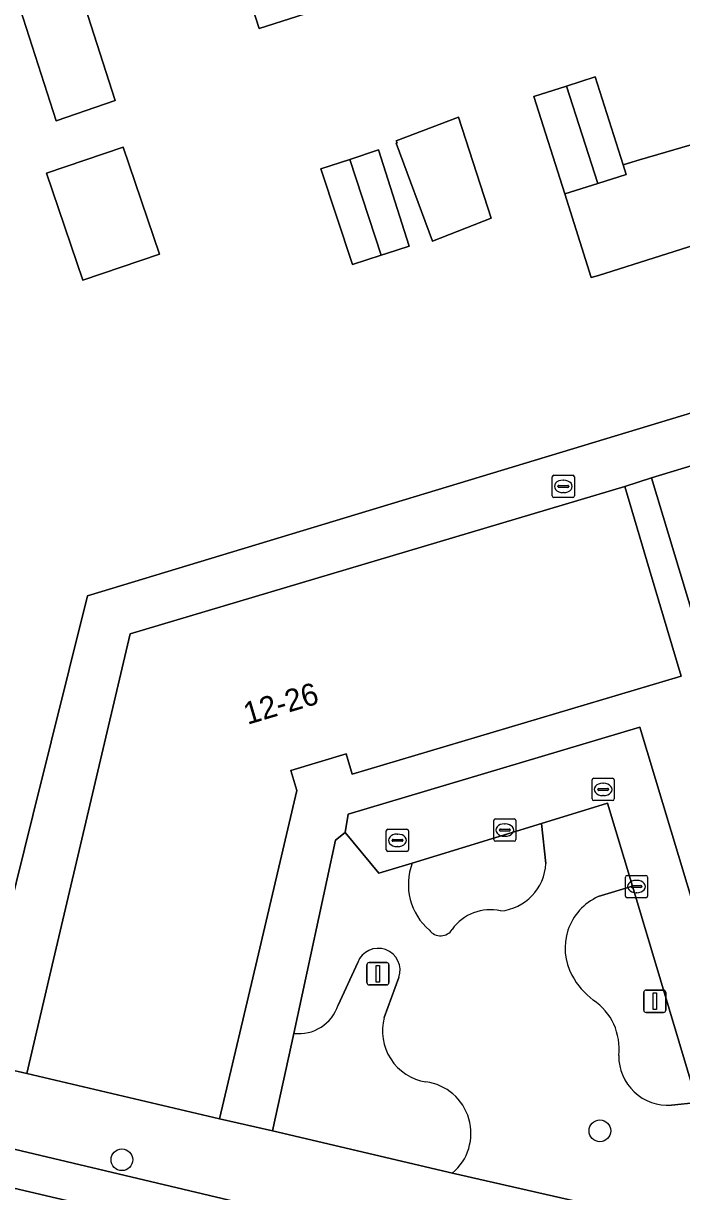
# Model space of a CAD drawing. Extents: x 159716 to 160783, y 383290 to 384031.
# Drawn here: x 160082.3 to 160111.9, y 383489.6 to 383542.1 of the extents above; entities that cross this region are included whole.
import ezdxf

# ---------------------------------------------------------------- set-up
doc = ezdxf.new("R2010")
doc.units = 0
for name, color, linetype in [('IMGEO_Boom', 7, 'Continuous'), ('IMGEO_Brandkraan', 7, 'Continuous'), ('IMGEO_Erf', 7, 'Continuous'), ('IMGEO_Groenvoorziening', 7, 'Continuous'), ('IMGEO_Hek', 7, 'Continuous'), ('IMGEO_Kolk', 7, 'Continuous'), ('IMGEO_Lichtmast', 7, 'Continuous'), ('IMGEO_Pand', 7, 'Continuous'), ('IMGEO_Pand_nummerreeks', 7, 'Continuous'), ('IMGEO_Parkeervlak_open', 7, 'Continuous'), ('IMGEO_Rijbaan_lokaal_open', 7, 'Continuous'), ('IMGEO_Rioolput', 7, 'Continuous'), ('IMGEO_Voetpad_open', 7, 'Continuous')]:
    doc.layers.add(name, color=color, linetype=linetype)

msp = doc.modelspace()

# ---------------------------------------------------------------- linework, layer by layer
at = {"layer": 'IMGEO_Boom'}
for centre in [(160108.178, 383492.298), (160086.689, 383490.997)]:
    msp.add_circle(centre, 0.489, dxfattribs=at)
at = {"layer": 'IMGEO_Brandkraan'}
for p, q in [((160106.033, 383520.85), (160106.033, 383521.702)), ((160106.108, 383521.776), (160106.96, 383521.776)), ((160106.521, 383521.556), (160106.546, 383521.556)), ((160107.034, 383521.702), (160107.034, 383520.85)), ((160106.292, 383521.27), (160106.292, 383521.282)), ((160106.73, 383521.233), (160106.332, 383521.233)), ((160106.335, 383521.319), (160106.733, 383521.319)), ((160106.544, 383520.996), (160106.519, 383520.996)), ((160106.776, 383521.282), (160106.776, 383521.27)), ((160106.96, 383520.776), (160106.108, 383520.776))]:
    msp.add_line(p, q, dxfattribs=at)
for points in [[(160106.033, 383520.85), (160106.033, 383521.702)], [(160106.108, 383521.776), (160106.96, 383521.776)], [(160107.034, 383521.702), (160107.034, 383520.85)], [(160106.96, 383520.776), (160106.108, 383520.776)]]:
    msp.add_lwpolyline(points, dxfattribs=at)
for centre, radius, start, end in [((160106.11, 383521.7), 0.0765, 91.552, 178.448), ((160106.11, 383521.7), 0.0765, 91.552, 178.448), ((160106.958, 383521.7), 0.0765, 1.552, 88.448), ((160106.958, 383521.7), 0.0765, 1.552, 88.448), ((160106.332, 383521.279), 0.0403, 85.8775, 175.7526), ((160106.329, 383521.269), 0.0366, 178.938, 274.7102), ((160106.733, 383521.276), 0.043, 264.8664, 352.4533), ((160106.737, 383521.281), 0.0386, 1.7309, 96.639), ((160106.11, 383520.852), 0.0765, 181.552, 268.448), ((160106.11, 383520.852), 0.0765, 181.552, 268.448), ((160106.958, 383520.852), 0.0765, 271.552, 358.448), ((160106.958, 383520.852), 0.0765, 271.552, 358.448)]:
    msp.add_arc(centre, radius, start, end, dxfattribs=at)
for centre, major_axis, ratio, start_param, end_param in [((160106.52, 383521.276), (-0.387, 0.002), 0.722429, 4.712389, 7.853982), ((160106.545, 383521.276), (-0.39, 0.002), 0.717154, 1.570796, 4.712389)]:
    msp.add_ellipse(centre, major_axis=major_axis, ratio=ratio, start_param=start_param, end_param=end_param, dxfattribs=at)
at = {"layer": 'IMGEO_Erf'}
for points in [[(160095.251, 383542.63), (160092.854, 383541.861), (160091.557, 383545.907)], [(160084.758, 383543.726), (160086.393, 383538.629), (160083.735, 383537.719), (160081.981, 383543.18)], [(160119.596, 383534.404), (160108.117, 383530.754), (160107.788, 383530.676), (160106.597, 383534.426), (160105.205, 383538.81), (160106.669, 383539.275), (160107.97, 383539.688), (160109.223, 383535.742), (160109.956, 383535.958), (160112.681, 383536.758)], [(160054.783, 383510.049), (160057.756, 383509.353), (160058.284, 383511.606), (160060.77, 383511.024), (160063.327, 383510.425), (160065.622, 383509.887), (160064.676, 383505.849), (160067.254, 383505.244), (160069.762, 383504.656), (160072.014, 383505.337), (160076.795, 383504.216), (160075.929, 383500.52), (160075.807, 383500), (160075.028, 383496.679), (160079.077, 383495.669), (160080.332, 383500.702), (160081.184, 383500.489), (160082.679, 383506.481), (160085.14, 383516.351), (160119.521, 383526.767)], [(160117.025, 383500), (160110.499, 383521.668), (160109.297, 383521.265), (160110.41, 383517.529), (160111.837, 383512.736), (160097.044, 383508.33), (160096.772, 383509.244), (160094.291, 383508.505), (160094.559, 383507.608), (160092.767, 383500), (160091.079, 383492.832), (160093.463, 383492.298), (160094.412, 383496.681), (160096.292, 383505.366), (160096.728, 383505.71), (160096.86, 383506.543), (160109.974, 383510.449), (160113.121, 383500)]]:
    msp.add_lwpolyline(points, dxfattribs=at)
for points in [[(160100.649, 383532.303), (160099.023, 383536.712), (160099.059, 383536.725), (160099.023, 383536.822), (160101.819, 383537.877), (160103.292, 383533.33)], [(160084.938, 383530.553), (160083.307, 383535.366), (160086.745, 383536.531), (160088.376, 383531.719)], [(160098.577, 383531.749), (160098.349, 383531.674), (160097.053, 383531.247), (160095.634, 383535.552), (160096.93, 383535.979), (160098.225, 383536.406), (160099.609, 383532.076)]]:
    msp.add_lwpolyline(points, close=True, dxfattribs=at)
at = {"layer": 'IMGEO_Groenvoorziening'}
for points in [[(160108.104, 383502.829), (160109.64, 383503.302), (160108.524, 383507.029), (160105.557, 383506.121), (160105.748, 383504.322)], [(160105.748, 383504.322), (160105.557, 383506.121), (160099.742, 383504.34)], [(160099.742, 383504.34), (160098.239, 383503.88), (160096.728, 383505.71), (160096.292, 383505.366), (160094.412, 383496.681)], [(160111.391, 383493.449), (160112.552, 383493.574), (160109.64, 383503.302), (160108.104, 383502.829)], [(160096.407, 383497.955), (160097.289, 383499.862)], [(160097.289, 383499.862), (160096.407, 383497.955)], [(160099.137, 383499.191), (160098.483, 383497.399)], [(160098.483, 383497.399), (160099.137, 383499.191)], [(160094.412, 383496.681), (160093.463, 383492.298), (160101.544, 383490.395)], [(160101.544, 383490.395), (160113.66, 383487.636), (160114.386, 383487.449), (160112.552, 383493.574), (160111.391, 383493.449)]]:
    msp.add_lwpolyline(points, dxfattribs=at)
for centre, radius, start, end in [((160102.281, 383503.38), 2.715, 159.2868, 229.5507), ((160102.281, 383503.38), 2.715, 159.2868, 229.5507), ((160103.498, 383504.426), 2.253, 275.4615, 357.365), ((160103.498, 383504.426), 2.253, 275.4615, 357.365), ((160109.158, 383500.51), 2.547, 114.4441, 208.618), ((160109.158, 383500.51), 2.547, 114.4441, 208.618), ((160103.234, 383500.172), 2.067, 76.6355, 145.1567), ((160103.234, 383500.172), 2.067, 76.6355, 145.1567), ((160101.015, 383501.693), 0.624, 217.455, 326.9329), ((160101.015, 383501.693), 0.624, 217.455, 326.9329), ((160098.211, 383499.522), 0.983, 340.3213, 159.7672), ((160098.211, 383499.522), 0.983, 340.3213, 159.7672), ((160109.951, 383500.93), 3.444, 208.4274, 233.0794), ((160109.951, 383500.93), 3.444, 208.4274, 233.0794), ((160094.645, 383498.516), 1.849, 262.7728, 342.3515), ((160094.645, 383498.516), 1.849, 262.7728, 342.3515), ((160106.403, 383495.989), 2.64, 353.2992, 55.9273), ((160106.403, 383495.989), 2.64, 353.2992, 55.9273), ((160100.718, 383496.789), 2.316, 164.7422, 261.0912), ((160100.718, 383496.789), 2.316, 164.7422, 261.0912), ((160111.241, 383495.66), 2.216, 179.4449, 273.8937), ((160111.241, 383495.66), 2.216, 179.4449, 273.8937), ((160100.048, 383492.187), 2.334, 309.8482, 82.3483), ((160100.048, 383492.187), 2.334, 309.8482, 82.3483)]:
    msp.add_arc(centre, radius, start, end, dxfattribs=at)
at = {"layer": 'IMGEO_Hek'}
msp.add_lwpolyline([(160109.956, 383535.958), (160109.223, 383535.742)], dxfattribs=at)
at = {"layer": 'IMGEO_Kolk'}
for p, q in [((160103.477, 383506.323), (160104.329, 383506.323)), ((160103.402, 383505.397), (160103.402, 383506.249)), ((160103.661, 383505.817), (160103.661, 383505.829)), ((160104.099, 383505.78), (160103.701, 383505.78)), ((160103.704, 383505.866), (160104.102, 383505.866)), ((160103.89, 383506.103), (160103.915, 383506.103)), ((160104.145, 383505.829), (160104.145, 383505.817)), ((160104.403, 383506.249), (160104.403, 383505.397)), ((160104.329, 383505.323), (160103.477, 383505.323)), ((160103.913, 383505.543), (160103.888, 383505.543)), ((160109.323, 383502.856), (160109.323, 383503.708)), ((160109.398, 383503.782), (160110.25, 383503.782)), ((160110.324, 383503.708), (160110.324, 383502.856)), ((160109.582, 383503.276), (160109.582, 383503.288)), ((160110.02, 383503.239), (160109.622, 383503.239)), ((160109.625, 383503.325), (160110.023, 383503.325)), ((160109.811, 383503.562), (160109.836, 383503.562)), ((160110.066, 383503.288), (160110.066, 383503.276)), ((160110.25, 383502.782), (160109.398, 383502.782)), ((160109.834, 383503.002), (160109.809, 383503.002))]:
    msp.add_line(p, q, dxfattribs=at)
for points in [[(160103.477, 383506.323), (160104.329, 383506.323)], [(160103.402, 383505.397), (160103.402, 383506.249)], [(160104.403, 383506.249), (160104.403, 383505.397)], [(160104.329, 383505.323), (160103.477, 383505.323)], [(160109.323, 383502.856), (160109.323, 383503.708)], [(160109.398, 383503.782), (160110.25, 383503.782)], [(160110.324, 383503.708), (160110.324, 383502.856)], [(160110.25, 383502.782), (160109.398, 383502.782)]]:
    msp.add_lwpolyline(points, dxfattribs=at)
for centre, radius, start, end in [((160103.479, 383506.247), 0.0765, 91.552, 178.448), ((160103.479, 383506.247), 0.0765, 91.552, 178.448), ((160104.327, 383506.247), 0.0765, 1.552, 88.448), ((160104.327, 383506.247), 0.0765, 1.552, 88.448), ((160103.701, 383505.826), 0.0403, 85.8775, 175.7526), ((160103.698, 383505.816), 0.0366, 178.938, 274.7102), ((160104.102, 383505.823), 0.043, 264.8664, 352.4533), ((160104.106, 383505.828), 0.0386, 1.7309, 96.639), ((160103.479, 383505.399), 0.0765, 181.552, 268.448), ((160103.479, 383505.399), 0.0765, 181.552, 268.448), ((160104.327, 383505.399), 0.0765, 271.552, 358.448), ((160104.327, 383505.399), 0.0765, 271.552, 358.448), ((160109.4, 383503.706), 0.0765, 91.552, 178.448), ((160109.4, 383503.706), 0.0765, 91.552, 178.448), ((160110.248, 383503.706), 0.0765, 1.552, 88.448), ((160110.248, 383503.706), 0.0765, 1.552, 88.448), ((160109.622, 383503.285), 0.0403, 85.8775, 175.7526), ((160109.619, 383503.275), 0.0366, 178.938, 274.7102), ((160110.023, 383503.282), 0.043, 264.8664, 352.4533), ((160110.027, 383503.287), 0.0386, 1.7309, 96.639), ((160109.4, 383502.858), 0.0765, 181.552, 268.448), ((160109.4, 383502.858), 0.0765, 181.552, 268.448), ((160110.248, 383502.858), 0.0765, 271.552, 358.448), ((160110.248, 383502.858), 0.0765, 271.552, 358.448)]:
    msp.add_arc(centre, radius, start, end, dxfattribs=at)
for centre, major_axis, ratio, start_param, end_param in [((160103.889, 383505.823), (-0.387, 0.002), 0.722429, 4.712389, 7.853982), ((160103.914, 383505.823), (-0.39, 0.002), 0.717154, 1.570796, 4.712389), ((160109.81, 383503.282), (-0.387, 0.002), 0.722429, 4.712389, 7.853982), ((160109.835, 383503.282), (-0.39, 0.002), 0.717154, 1.570796, 4.712389)]:
    msp.add_ellipse(centre, major_axis=major_axis, ratio=ratio, start_param=start_param, end_param=end_param, dxfattribs=at)
at = {"layer": 'IMGEO_Lichtmast'}
for p, q in [((160097.705, 383498.961), (160097.705, 383499.761)), ((160097.705, 383499.761), (160097.705, 383498.961)), ((160097.805, 383499.861), (160098.595, 383499.861)), ((160098.595, 383499.861), (160097.805, 383499.861)), ((160098.695, 383499.761), (160098.695, 383498.961)), ((160098.695, 383498.961), (160098.695, 383499.761)), ((160098.595, 383498.861), (160097.805, 383498.861)), ((160097.805, 383498.861), (160098.595, 383498.861)), ((160110.151, 383497.725), (160110.151, 383498.525)), ((160110.151, 383498.525), (160110.151, 383497.725)), ((160110.251, 383498.625), (160111.041, 383498.625)), ((160111.041, 383498.625), (160110.251, 383498.625)), ((160111.141, 383498.525), (160111.141, 383497.725)), ((160111.141, 383497.725), (160111.141, 383498.525)), ((160111.041, 383497.625), (160110.251, 383497.625)), ((160110.251, 383497.625), (160111.041, 383497.625))]:
    msp.add_line(p, q, dxfattribs=at)
for points in [[(160098.125, 383499.736), (160098.275, 383499.736), (160098.275, 383498.986), (160098.125, 383498.986), (160098.125, 383499.736)], [(160110.571, 383498.5), (160110.721, 383498.5), (160110.721, 383497.75), (160110.571, 383497.75), (160110.571, 383498.5)]]:
    msp.add_lwpolyline(points, dxfattribs=at)
for centre, start, end in [((160097.805, 383499.761), 90, 180), ((160097.805, 383499.761), 90, 180), ((160098.595, 383499.761), 0, 90), ((160098.595, 383499.761), 360, 90), ((160097.805, 383498.961), 180, 270), ((160097.805, 383498.961), 180, 270), ((160098.595, 383498.961), 270, 0), ((160098.595, 383498.961), 270, 0), ((160110.251, 383498.525), 90, 180), ((160110.251, 383498.525), 90, 180), ((160111.041, 383498.525), 0, 90), ((160111.041, 383498.525), 360, 90), ((160110.251, 383497.725), 180, 270), ((160110.251, 383497.725), 180, 270), ((160111.041, 383497.725), 270, 0), ((160111.041, 383497.725), 270, 0)]:
    msp.add_arc(centre, 0.1, start, end, dxfattribs=at)
at = {"layer": 'IMGEO_Pand'}
for points in [[(160091.569, 383554.115), (160086.838, 383552.595), (160089.17, 383545.319), (160089.222, 383545.158), (160091.557, 383545.907), (160092.854, 383541.861), (160095.251, 383542.63), (160095.217, 383542.738)], [(160086.838, 383552.595), (160086.347, 383552.437), (160086.102, 383553.199), (160081.748, 383551.798), (160082.75, 383548.674), (160080.454, 383547.938), (160081.981, 383543.18), (160083.735, 383537.719), (160086.393, 383538.629), (160084.758, 383543.726), (160089.222, 383545.158), (160089.17, 383545.319)], [(160108.088, 383534.899), (160109.362, 383535.304), (160109.223, 383535.742), (160107.97, 383539.688), (160106.669, 383539.275)], [(160108.088, 383534.899), (160106.669, 383539.275), (160105.205, 383538.81), (160106.597, 383534.426)], [(160101.819, 383537.877), (160099.023, 383536.822), (160099.059, 383536.725), (160099.023, 383536.712), (160100.649, 383532.303), (160103.292, 383533.33)], [(160084.938, 383530.553), (160088.376, 383531.719), (160086.745, 383536.531), (160083.307, 383535.366)], [(160096.93, 383535.979), (160098.349, 383531.674), (160098.577, 383531.749), (160099.609, 383532.076), (160098.225, 383536.406)], [(160096.93, 383535.979), (160095.634, 383535.552), (160097.053, 383531.247), (160098.349, 383531.674)], [(160119.047, 383524.242), (160115.287, 383523.11), (160110.499, 383521.668), (160117.025, 383500), (160118.898, 383494.078), (160127.557, 383492.028), (160129.624, 383500.686), (160125.923, 383501.413)], [(160082.411, 383494.873), (160091.079, 383492.832), (160092.767, 383500), (160094.559, 383507.608), (160094.291, 383508.505), (160096.772, 383509.244), (160097.044, 383508.33), (160111.837, 383512.736), (160110.41, 383517.529), (160109.297, 383521.265), (160087.065, 383514.643), (160083.618, 383500)]]:
    msp.add_lwpolyline(points, close=True, dxfattribs=at)
at = {"layer": 'IMGEO_Parkeervlak_open'}
for points in [[(160030.39, 383501.718), (160037.998, 383500), (160115.615, 383481.783), (160115.214, 383481.919), (160114.99, 383482.038), (160114.733, 383482.223), (160114.438, 383482.525), (160114.058, 383483.274)], [(160113.335, 383484.024), (160092.655, 383488.916), (160074.56, 383493.196)]]:
    msp.add_lwpolyline(points, dxfattribs=at)
at = {"layer": 'IMGEO_Rijbaan_lokaal_open'}
msp.add_lwpolyline([(160112.681, 383536.758), (160109.956, 383535.958), (160109.223, 383535.742), (160109.362, 383535.304), (160108.088, 383534.899), (160106.597, 383534.426), (160107.788, 383530.676), (160108.117, 383530.754), (160119.596, 383534.404)], dxfattribs=at)
msp.add_lwpolyline([(160037.998, 383500), (160030.39, 383501.718), (160026.229, 383503.016), (160025.764, 383503.184), (160025.553, 383503.261), (160025.287, 383503.349), (160023.952, 383498.899), (160026.851, 383497.979), (160029.484, 383497.298), (160049.062, 383492.672), (160049.223, 383492.632), (160052.896, 383491.782), (160053.073, 383491.741), (160075.473, 383486.534), (160076.614, 383486.267), (160114.655, 383477.395), (160114.912, 383477.335), (160115.92, 383481.713), (160115.615, 383481.783)], close=True, dxfattribs=at)
at = {"layer": 'IMGEO_Rioolput'}
for p, q in [((160107.824, 383507.224), (160107.824, 383508.076)), ((160107.899, 383508.15), (160108.751, 383508.15)), ((160108.312, 383507.93), (160108.337, 383507.93)), ((160108.825, 383508.076), (160108.825, 383507.224)), ((160108.083, 383507.644), (160108.083, 383507.656)), ((160108.521, 383507.607), (160108.123, 383507.607)), ((160108.126, 383507.693), (160108.524, 383507.693)), ((160108.335, 383507.37), (160108.31, 383507.37)), ((160108.567, 383507.656), (160108.567, 383507.644)), ((160108.751, 383507.15), (160107.899, 383507.15)), ((160098.575, 383504.934), (160098.575, 383505.786)), ((160098.65, 383505.86), (160099.502, 383505.86)), ((160099.576, 383505.786), (160099.576, 383504.934)), ((160098.834, 383505.354), (160098.834, 383505.366)), ((160099.272, 383505.317), (160098.874, 383505.317)), ((160098.877, 383505.403), (160099.275, 383505.403)), ((160099.063, 383505.64), (160099.088, 383505.64)), ((160099.318, 383505.366), (160099.318, 383505.354)), ((160099.502, 383504.86), (160098.65, 383504.86)), ((160099.086, 383505.08), (160099.061, 383505.08))]:
    msp.add_line(p, q, dxfattribs=at)
for points in [[(160107.824, 383507.224), (160107.824, 383508.076)], [(160107.899, 383508.15), (160108.751, 383508.15)], [(160108.825, 383508.076), (160108.825, 383507.224)], [(160108.751, 383507.15), (160107.899, 383507.15)], [(160098.575, 383504.934), (160098.575, 383505.786)], [(160098.65, 383505.86), (160099.502, 383505.86)], [(160099.576, 383505.786), (160099.576, 383504.934)], [(160099.502, 383504.86), (160098.65, 383504.86)]]:
    msp.add_lwpolyline(points, dxfattribs=at)
for centre, radius, start, end in [((160107.901, 383508.074), 0.0765, 91.552, 178.448), ((160107.901, 383508.074), 0.0765, 91.552, 178.448), ((160108.749, 383508.074), 0.0765, 1.552, 88.448), ((160108.749, 383508.074), 0.0765, 1.552, 88.448), ((160108.123, 383507.653), 0.0403, 85.8775, 175.7526), ((160108.12, 383507.643), 0.0366, 178.938, 274.7102), ((160108.524, 383507.65), 0.043, 264.8664, 352.4533), ((160108.528, 383507.655), 0.0386, 1.7309, 96.639), ((160107.901, 383507.226), 0.0765, 181.552, 268.448), ((160107.901, 383507.226), 0.0765, 181.552, 268.448), ((160108.749, 383507.226), 0.0765, 271.552, 358.448), ((160108.749, 383507.226), 0.0765, 271.552, 358.448), ((160098.652, 383505.784), 0.0765, 91.552, 178.448), ((160098.652, 383505.784), 0.0765, 91.552, 178.448), ((160099.5, 383505.784), 0.0765, 1.552, 88.448), ((160099.5, 383505.784), 0.0765, 1.552, 88.448), ((160098.874, 383505.363), 0.0403, 85.8775, 175.7526), ((160098.871, 383505.353), 0.0366, 178.938, 274.7102), ((160099.275, 383505.36), 0.043, 264.8664, 352.4533), ((160099.279, 383505.365), 0.0386, 1.7309, 96.639), ((160098.652, 383504.936), 0.0765, 181.552, 268.448), ((160098.652, 383504.936), 0.0765, 181.552, 268.448), ((160099.5, 383504.936), 0.0765, 271.552, 358.448), ((160099.5, 383504.936), 0.0765, 271.552, 358.448)]:
    msp.add_arc(centre, radius, start, end, dxfattribs=at)
for centre, major_axis, ratio, start_param, end_param in [((160108.311, 383507.65), (-0.387, 0.002), 0.722429, 4.712389, 7.853982), ((160108.336, 383507.65), (-0.39, 0.002), 0.717154, 1.570796, 4.712389), ((160099.062, 383505.36), (-0.387, 0.002), 0.722429, 4.712389, 7.853982), ((160099.087, 383505.36), (-0.39, 0.002), 0.717154, 1.570796, 4.712389)]:
    msp.add_ellipse(centre, major_axis=major_axis, ratio=ratio, start_param=start_param, end_param=end_param, dxfattribs=at)
at = {"layer": 'IMGEO_Voetpad_open'}
for points in [[(160109.297, 383521.265), (160110.499, 383521.668), (160115.287, 383523.11), (160119.047, 383524.242), (160120.182, 383524.584), (160120.143, 383524.713), (160119.521, 383526.767), (160085.14, 383516.351), (160082.679, 383506.481), (160081.184, 383500.489), (160080.332, 383500.702), (160079.077, 383495.669), (160080.57, 383495.297), (160082.411, 383494.873), (160083.618, 383500), (160087.065, 383514.643)], [(160109.974, 383510.449), (160096.86, 383506.543), (160096.728, 383505.71), (160098.239, 383503.88), (160099.742, 383504.34), (160105.557, 383506.121), (160108.524, 383507.029), (160109.64, 383503.302), (160112.552, 383493.574), (160114.386, 383487.449), (160117.113, 383486.747), (160113.121, 383500)]]:
    msp.add_lwpolyline(points, close=True, dxfattribs=at)
for points in [[(160101.544, 383490.395), (160093.463, 383492.298), (160091.079, 383492.832), (160082.411, 383494.873), (160080.57, 383495.297), (160079.077, 383495.669), (160075.028, 383496.679), (160074.787, 383495.652), (160071.598, 383496.4), (160071.406, 383495.583), (160065.323, 383497.009), (160060.461, 383498.149), (160055.301, 383499.358), (160055.451, 383500), (160055.497, 383500.195), (160052.629, 383500.867), (160052.735, 383501.318), (160024.822, 383509.46), (160020.706, 383510.759), (160020.471, 383510.144)], [(160033.63, 383502.95), (160051.319, 383498.726), (160051.408, 383499.106), (160055.09, 383498.247), (160054.996, 383497.847), (160070.904, 383494.048), (160071.018, 383494.535), (160074.674, 383493.682), (160074.56, 383493.196), (160092.655, 383488.916), (160113.335, 383484.024)], [(160194.475, 383480.623), (160194.15, 383481.64), (160192.457, 383481.099), (160168.912, 383473.579), (160150.634, 383478.026), (160150.838, 383478.892), (160149.777, 383479.145), (160149.116, 383479.302), (160147.229, 383479.752), (160134.066, 383482.891), (160131.838, 383483.422), (160127.298, 383484.43), (160117.113, 383486.747), (160114.386, 383487.449), (160113.66, 383487.636), (160101.544, 383490.395)]]:
    msp.add_lwpolyline(points, dxfattribs=at)

# ---------------------------------------------------------------- texts
at = {"layer": 'IMGEO_Pand_nummerreeks'}
msp.add_text('12-26', height=1, rotation=16.5869, dxfattribs=at).set_placement((160092.335, 383510.552))

doc.saveas('drawing.dxf')
